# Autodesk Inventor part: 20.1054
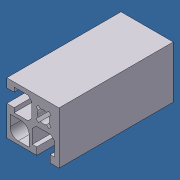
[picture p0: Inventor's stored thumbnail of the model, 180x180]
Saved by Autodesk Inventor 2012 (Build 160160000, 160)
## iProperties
Created: 2007-07
Part Number: 20.1054
Material: Aluminum-6061
Document SubType Name: Modeling
Designer: Andy Moles
Density: 2.71 g/cm^3
Description: LENGTH = 2.756"
Vendor: F
Stock Number: 32x32 F PROFILE
Mass: 91.4965 g
Surface Area: 210.175 cm^2
Volume: 33.7625 cm^3
Author: Andy Moles
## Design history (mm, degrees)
sketch "Sketch1"
  geometry: L1 (-20.5, -8.8)-(-13.8, -8.8) reference; L2 (-8.8, -13.8)-(-8.8, -20.5) reference; L3 (-8.8, -20.5)-(-15.5, -20.5) reference; L4 (-20.5, -15.5)-(-20.5, -8.8) reference; L5 (-4.596, -3.182)-(-3.263, -1.849) reference; L6 (-3.263, 1.849)-(-4.596, 3.182) reference; L7 (-3.182, 4.596)-(-1.849, 3.263) reference; L8 (1.849, 3.263)-(3.182, 4.596) reference; L9 (4.596, 3.182)-(3.263, 1.849) reference; L10 (3.263, -1.849)-(4.596, -3.182) reference; L11 (4.596, -3.182)-(3.182, -4.596) reference; L12 (3.182, -4.596)-(1.849, -3.263) reference; L13 (-1.849, -3.263)-(-3.182, -4.596) reference; L14 (-3.182, -4.596)-(-4.596, -3.182) reference; L15 (-4.1, -22.5)-(-4.1, -18) reference; L16 (-6.8, -18)-(-6.8, -9.5) reference; L17 (-6.8, -9.5)-(-4.5, -7.2) reference; L18 (-4.5, -7.2)-(4.5, -7.2) reference; L19 (4.5, -7.2)-(6.8, -9.5) reference; L20 (6.8, -9.5)-(6.8, -18) reference; L21 (6.8, -18)-(4.6, -18) reference; L22 (4.1, -18)-(4.1, -22.5) reference; L23 (9.5, -22.5)-(4.4, -22.5) reference; L24 (9.5, 9.5)-(9.5, -22.5) reference; L25 (-22.5, 9.5)-(9.5, 9.5) reference; L26 (-22.5, 4.4)-(-22.5, 9.5) reference; L27 (-22.5, 4.1)-(-18, 4.1) reference; L28 (-18, 4.6)-(-18, 6.8) reference; L29 (-18, 6.8)-(-9.5, 6.8) reference; L30 (-9.5, 6.8)-(-7.2, 4.5) reference; L31 (-7.2, 4.5)-(-7.2, -4.5) reference; L32 (-7.2, -4.5)-(-9.5, -6.8) reference; L33 (-9.5, -6.8)-(-18, -6.8) reference; L34 (-18, -4.1)-(-22.5, -4.1) reference; L35 (-22.5, -22.5)-(-22.5, -4.1) reference; L36 (-22.5, 4.1)-(-22.5, 4.4) reference; L37 (-18, -6.8)-(-18, -4.1) reference; L38 (-18, 4.1)-(-18, 4.6) reference; L39 (4.6, -18)-(4.1, -18) reference; L40 (-4.1, -18)-(-6.8, -18) reference; L41 (4.4, -22.5)-(4.1, -22.5) reference; L42 (-4.1, -22.5)-(-22.5, -22.5) reference; L43 (-4.596, 3.182)-(-3.182, 4.596) reference; L44 (3.182, 4.596)-(4.596, 3.182) reference; A1 r 5 centre (-13.8, -13.8) between (-8.8, -13.8) and (-13.8, -8.8) reference; A2 r 5 centre (-15.5, -15.5) between (-20.5, -15.5) and (-15.5, -20.5) reference; A3 r 3.75 centre (0, 0) between (-3.263, 1.849) and (-3.263, -1.849) reference; A4 r 3.75 centre (0, 0) between (1.849, 3.263) and (-1.849, 3.263) reference; A5 r 3.75 centre (0, 0) between (3.263, -1.849) and (3.263, 1.849) reference; A6 r 3.75 centre (0, 0) between (-1.849, -3.263) and (1.849, -3.263) reference
  constraints: 88 end point, 14 horizontal, 14 vertical, 12 point on circle, 6 centre point, 78 other
extrude "Extrusion1" new body sketch "Sketch1" stored distance "d0" = 70; taper "d1" = 0 deg
body "Solid1"
